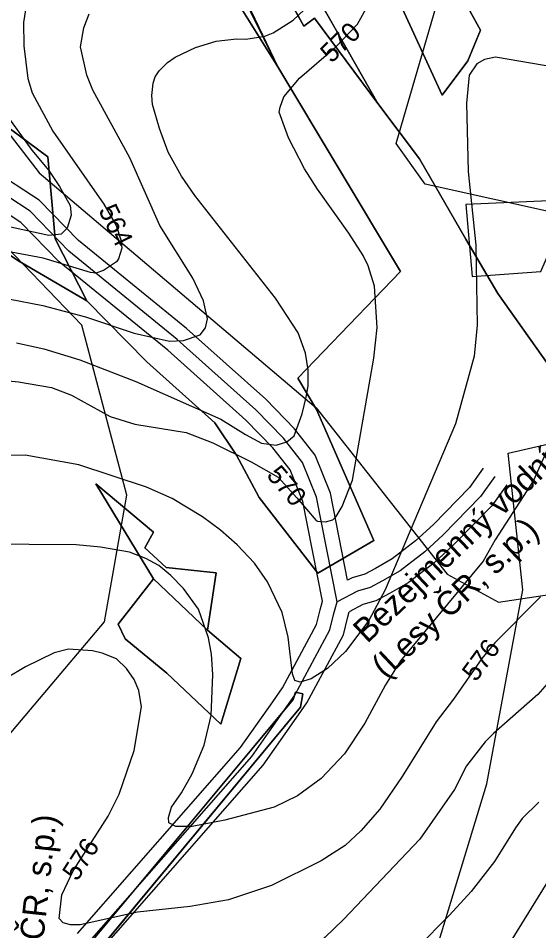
# Model space of a CAD drawing. Extents: x -709418 to -703832, y -1161719 to -1157826.
# Drawn here: x -707249.8 to -707032.1, y -1159514.6 to -1159133.3 of the extents above; entities that cross this region are included whole.
import ezdxf

# ---------------------------------------------------------------- set-up
doc = ezdxf.new("R2010")
doc.units = 0
for name, color, linetype in [('102_obvod PÚ', 7, 'Continuous'), ('106_zastavitelné plochy', 7, 'Continuous'), ('120_vrstevnice hlavní', 7, 'Continuous'), ('121_vrstevnice hlavní_popis', 7, 'Continuous'), ('122_vrstevnice základní', 7, 'Continuous'), ('206_TTP_KN', 7, 'Continuous'), ('207_lesní pozemek_KN', 7, 'Continuous'), ('208_vodní plocha_KN', 7, 'Continuous'), ('210_ostatní plocha_KN', 7, 'Continuous'), ('501_vodní tok', 7, 'Continuous'), ('502_vodní tok_popis', 7, 'Continuous'), ('514 odvodnění - LPIS', 7, 'Continuous'), ('735_OP sítí TI', 7, 'Continuous')]:
    doc.layers.add(name, color=color, linetype=linetype)

msp = doc.modelspace()

# ---------------------------------------------------------------- linework, layer by layer
at = {"layer": '102_obvod PÚ'}
for points in [[(-707090.72, -1159125.66), (-707080.09, -1159102.97), (-707083.45, -1159098.68), (-707081.52, -1159086.91), (-707067.53, -1159081.2), (-707060.25, -1159112.67), (-707060.75, -1159130.51), (-707056.4, -1159138.22), (-707061.68, -1159151.06), (-707072.46, -1159165.41), (-707090.72, -1159125.66)], [(-707090.72, -1159125.66), (-707072.46, -1159165.41), (-707061.68, -1159151.06), (-707056.4, -1159138.22), (-707060.75, -1159130.51), (-707060.25, -1159112.67), (-707067.53, -1159081.2), (-707081.52, -1159086.91), (-707083.45, -1159098.68), (-707080.09, -1159102.97), (-707090.72, -1159125.66)], [(-707163.88, -1159107.46), (-707141.26, -1159153.59), (-707089.94, -1159239.07), (-707132.85, -1159283.71), (-707125, -1159296.84), (-707101.06, -1159351.57), (-707124.48, -1159365.16), (-707148.94, -1159333.63), (-707158.47, -1159315.9), (-707167.56, -1159302.38), (-707196, -1159276.9), (-707221.11, -1159251.31), (-707234.26, -1159225.46), (-707237.4, -1159191.19), (-707264.49, -1159171.23), (-707284.79, -1159147.72)], [(-707284.79, -1159147.72), (-707264.49, -1159171.23), (-707237.4, -1159191.19), (-707234.26, -1159225.46), (-707221.11, -1159251.31), (-707196, -1159276.9), (-707167.56, -1159302.38), (-707158.47, -1159315.9), (-707148.94, -1159333.63), (-707124.48, -1159365.16), (-707101.06, -1159351.57), (-707125, -1159296.84), (-707132.85, -1159283.71), (-707089.94, -1159239.07), (-707141.26, -1159153.59), (-707163.88, -1159107.46)], [(-707207.97, -1159386.5), (-707193.13, -1159367.53), (-707170.58, -1159389.04), (-707156.7, -1159400.84), (-707165.01, -1159428.35), (-707187.56, -1159406.94), (-707205.04, -1159392.67), (-707207.97, -1159386.5)], [(-707207.97, -1159386.5), (-707205.04, -1159392.67), (-707187.56, -1159406.94), (-707165.01, -1159428.35), (-707156.7, -1159400.84), (-707170.58, -1159389.04), (-707193.13, -1159367.53), (-707207.97, -1159386.5)]]:
    msp.add_lwpolyline(points, dxfattribs=at)
at = {"layer": '106_zastavitelné plochy'}
for points in [[(-707062.59, -1159211.18), (-707059.86, -1159241.16), (-707031.23, -1159239.12), (-707018.28, -1159209.13), (-707062.59, -1159211.18)], [(-707081, -1159542.58), (-707053.73, -1159453.31), (-707038.73, -1159372.22), (-707044.86, -1159314.98), (-707006, -1159306.12), (-706981.46, -1159408.34), (-706987.6, -1159458.77), (-707002.6, -1159535.09), (-706999.87, -1159572.57), (-707008.73, -1159578.02), (-707010.09, -1159567.12), (-707032.59, -1159588.24), (-707046.91, -1159588.92), (-707081, -1159542.58)]]:
    msp.add_lwpolyline(points, dxfattribs=at)
at = {"layer": '120_vrstevnice hlavní'}
for points in [[(-707125.17, -1159343.19), (-707124.61, -1159343.46), (-707121.27, -1159343.74), (-707118.2, -1159342.91), (-707116.81, -1159341.51), (-707114.3, -1159337.33), (-707110, -1159326.39), (-707101, -1159275.31), (-707099.71, -1159262.46), (-707100.71, -1159245.31), (-707103.43, -1159236.74), (-707105.57, -1159232.46), (-707111.43, -1159223.03), (-707124.57, -1159204.74), (-707130, -1159196.17), (-707136.71, -1159183.31), (-707140.57, -1159172.59), (-707140.28, -1159170.45), (-707138.71, -1159166.17), (-707132.14, -1159158.31), (-707117, -1159145.17), (-707107.85, -1159135.74), (-707102.85, -1159126.74)], [(-707256.43, -1159284.6), (-707249.58, -1159285.17), (-707235.86, -1159287.6), (-707227.43, -1159290.74), (-707211.29, -1159299.74), (-707201, -1159302.89), (-707179.57, -1159306.46), (-707168.43, -1159310.74), (-707152.28, -1159318.6), (-707141, -1159325.03), (-707133.25, -1159333.71), (-707125.17, -1159343.19)], [(-707031.99, -1159460.89), (-707038.99, -1159467.75), (-707041.85, -1159471.61), (-707050.56, -1159485.74), (-707060.33, -1159498.29), (-707069.45, -1159508.09), (-707096.49, -1159535.5)]]:
    msp.add_lwpolyline(points, dxfattribs=at)
at = {"layer": '122_vrstevnice základní'}
for points in [[(-707200.52, -1159285.11), (-707165.03, -1159300.87), (-707154.72, -1159307.28), (-707148.03, -1159310.91), (-707141.89, -1159311.74), (-707137.44, -1159310.35), (-707134.37, -1159307.84), (-707131.02, -1159298.64), (-707129.35, -1159291.67), (-707128.52, -1159286.93), (-707128.57, -1159280.17), (-707129.57, -1159273.31), (-707132.71, -1159264.74), (-707142.14, -1159250.31), (-707175.86, -1159207.31), (-707181.43, -1159199.31), (-707187, -1159189.31), (-707190.71, -1159179.31), (-707193.57, -1159169.31), (-707193.86, -1159165.59), (-707193.29, -1159160.45), (-707192.43, -1159157.74), (-707190.86, -1159155.31), (-707187.29, -1159151.74), (-707184.14, -1159149.59), (-707175.57, -1159145.45), (-707167, -1159142.88), (-707158.43, -1159141.88), (-707154.56, -1159142.04), (-707146.57, -1159140.74), (-707143.14, -1159139.31), (-707134.71, -1159134.02), (-707118.28, -1159118.45)], [(-707271.43, -1159130.45), (-707271.29, -1159139.88), (-707269, -1159147.88), (-707264.29, -1159157.88), (-707254.57, -1159173.88), (-707244, -1159188.45), (-707237, -1159196.88), (-707232.43, -1159203.6), (-707228, -1159211.6), (-707227.57, -1159215.6), (-707229.29, -1159221.03), (-707231.86, -1159223.45), (-707237, -1159224.03), (-707265.3, -1159217.9), (-707277.07, -1159216.13)], [(-707246.43, -1159127.88), (-707247.57, -1159135.02), (-707247.43, -1159144.74), (-707245.72, -1159158.45), (-707243.86, -1159164.45), (-707235.29, -1159180.45), (-707214, -1159211.03), (-707208.86, -1159219.88), (-707206.86, -1159225.88), (-707206.43, -1159229.31), (-707207.86, -1159233.88), (-707208.72, -1159235.03), (-707214.14, -1159238.74), (-707217.29, -1159239.88), (-707219.57, -1159239.6), (-707239.37, -1159233.52), (-707254.88, -1159230.62)], [(-706978.28, -1159127.59), (-706994.13, -1159142.74), (-707000.13, -1159147.31), (-707006.71, -1159150.88), (-707011.28, -1159152.59), (-707018.14, -1159153.88), (-707024.99, -1159153.88), (-707050.14, -1159149.59), (-707054.71, -1159150.45), (-707057.99, -1159152.31), (-707061.14, -1159157.02), (-707062.28, -1159168.74), (-707061.57, -1159197.31), (-707058.42, -1159228.17), (-707057.85, -1159261.6), (-707059.14, -1159274.46), (-707066.85, -1159302.74), (-707096.28, -1159372.18)], [(-707253.79, -1159250.6), (-707239.5, -1159253.32), (-707221.59, -1159258.1), (-707201.26, -1159264.94), (-707186.49, -1159268.24), (-707180.64, -1159267.96), (-707173.71, -1159265.6), (-707171.44, -1159262.67), (-707170.57, -1159258.88), (-707172.29, -1159251.31), (-707176.71, -1159241.88), (-707190.57, -1159219.88), (-707203.14, -1159191.6), (-707218.57, -1159163.31), (-707221, -1159157.02), (-707223.72, -1159145.17), (-707222.29, -1159137.31), (-707220.15, -1159131.45)], [(-707250.44, -1159268.88), (-707239.08, -1159271.44), (-707223.94, -1159276.05), (-707200.52, -1159285.11)], [(-707027.99, -1159312.46), (-707034.28, -1159326.46), (-707050.28, -1159351.32), (-707055.28, -1159360.18), (-707089.85, -1159401.89), (-707096.14, -1159411.89), (-707104.85, -1159427.89), (-707113.28, -1159440.75), (-707123, -1159451.04), (-707133, -1159458.32), (-707142.71, -1159463.04), (-707163.29, -1159468.47), (-707177, -1159471.04), (-707183.86, -1159471.04), (-707186.71, -1159469.61), (-707186.86, -1159467.32), (-707185.71, -1159463.04), (-707181.43, -1159457.04), (-707177, -1159449.04), (-707172, -1159437.04), (-707169.14, -1159424.75), (-707168.43, -1159407.61), (-707169, -1159399.03), (-707170.14, -1159392.18), (-707174.43, -1159380.18), (-707180.71, -1159371.6), (-707186, -1159366.18), (-707191, -1159362.03), (-707196.43, -1159359.03), (-707203.29, -1159356.46), (-707215.29, -1159354.32), (-707225.57, -1159353.32), (-707265, -1159353.03)], [(-707096.28, -1159372.18), (-707103.14, -1159385.03), (-707112.85, -1159397.89), (-707120.43, -1159405.03), (-707127.28, -1159409.32), (-707131.85, -1159410.75), (-707134.14, -1159410.03), (-707135, -1159407.32), (-707136.85, -1159391.89), (-707139.43, -1159381.6), (-707145.57, -1159368.75), (-707151, -1159361.03), (-707158.14, -1159353.32), (-707165.14, -1159347.17), (-707172.71, -1159341.6), (-707185.43, -1159334.03), (-707196.14, -1159329.32), (-707224.43, -1159319.89), (-707246.89, -1159315.83), (-707261.84, -1159316.2)], [(-707031.28, -1159375.03), (-707050.42, -1159394.32), (-707055.85, -1159400.89), (-707067.71, -1159417.89), (-707074.99, -1159427.32), (-707089.14, -1159450.18), (-707098.57, -1159463.89), (-707106.42, -1159472.9), (-707113, -1159479.04), (-707123, -1159485.47), (-707143.85, -1159495.75), (-707161.86, -1159501.75), (-707177.86, -1159504.47), (-707199.86, -1159506.9), (-707223.86, -1159512.18), (-707227.86, -1159512.18), (-707231, -1159511.32), (-707232.57, -1159509.47), (-707231.57, -1159499.61), (-707226.72, -1159489.61), (-707212.14, -1159466.75), (-707207.57, -1159457.61), (-707201.29, -1159439.32), (-707198.14, -1159421.04), (-707199.29, -1159414.18), (-707201.29, -1159409.61), (-707204.43, -1159405.03), (-707208.72, -1159401.03), (-707214.72, -1159398.6), (-707218.72, -1159397.6), (-707228.72, -1159397.03), (-707234.72, -1159398.46), (-707246.72, -1159404.32), (-707254.72, -1159409.03)], [(-707016.85, -1159398.03), (-707032.42, -1159415.89), (-707050.99, -1159432.18), (-707054.42, -1159435.75), (-707062.28, -1159445.75), (-707067.28, -1159455.61), (-707081.85, -1159476.32), (-707113.73, -1159510.01), (-707121.54, -1159517.53), (-707136.55, -1159530.6)], [(-707024.71, -1159488.04), (-707044.05, -1159519.36), (-707058.68, -1159540.12)]]:
    msp.add_lwpolyline(points, dxfattribs=at)
at = {"layer": '206_TTP_KN'}
for p, q in [((-707217.27, -1159327.83), (-707193.15, -1159348.1)), ((-707193.13, -1159367.53), (-707217.27, -1159327.83)), ((-707193.15, -1159348.1), (-707196.77, -1159354.61)), ((-707196.77, -1159354.61), (-707187.89, -1159362.89)), ((-707187.89, -1159362.89), (-707166.98, -1159365.07)), ((-707170.58, -1159389.04), (-707193.13, -1159367.53)), ((-707166.98, -1159365.07), (-707170.58, -1159389.04))]:
    msp.add_line(p, q, dxfattribs=at)
for points in [[(-707163.23, -1159076.48), (-707130.37, -1159136.64), (-707125.81, -1159133.29), (-707099.33, -1159168.86), (-707082, -1159191.97), (-707062.59, -1159225.65), (-707049.17, -1159248.27), (-707028.19, -1159278.03)], [(-707090.72, -1159125.66), (-707072.46, -1159165.41), (-707061.68, -1159151.06), (-707056.4, -1159138.22), (-707060.75, -1159130.51), (-707060.25, -1159112.67), (-707067.53, -1159081.2), (-707081.52, -1159086.91), (-707083.45, -1159098.68), (-707080.09, -1159102.97), (-707090.72, -1159125.66)], [(-707016.26, -1159123.62), (-706985.49, -1159170.3), (-707014.99, -1159245.85), (-707017.92, -1159260.69), (-707009.21, -1159302.72), (-707014.36, -1159296.7), (-707019.13, -1159291.16), (-707028.19, -1159278.03), (-707049.17, -1159248.27), (-707062.59, -1159225.65), (-707082, -1159191.97), (-707099.33, -1159168.86), (-707112.14, -1159146.31), (-707131.59, -1159112.27)], [(-707470.01, -1159128.4), (-707440.09, -1159137.73), (-707419.92, -1159149.19), (-707419.85, -1159160.97), (-707396.66, -1159177.74), (-707367.26, -1159195.86), (-707316.09, -1159206.21), (-707285.26, -1159210.99), (-707249.87, -1159234.47), (-707221.11, -1159251.31), (-707196, -1159276.9), (-707167.56, -1159302.38), (-707158.47, -1159315.9), (-707148.94, -1159333.63), (-707124.48, -1159365.16), (-707101.06, -1159351.57), (-707125, -1159296.84), (-707132.85, -1159283.71), (-707089.94, -1159239.07), (-707141.26, -1159153.59), (-707153.99, -1159126.87)], [(-707217.27, -1159327.83), (-707193.13, -1159367.53), (-707207.97, -1159386.5), (-707205.04, -1159392.67), (-707187.56, -1159406.94), (-707165.01, -1159428.35), (-707156.7, -1159400.84), (-707170.58, -1159389.04), (-707166.98, -1159365.07), (-707187.89, -1159362.89), (-707196.77, -1159354.61), (-707193.15, -1159348.1), (-707217.27, -1159327.83)], [(-707221.95, -1159529.79), (-707131.68, -1159421.18), (-707130.76, -1159415.61), (-707133.83, -1159414.9), (-707134.75, -1159417.97), (-707223.19, -1159524.06)]]:
    msp.add_lwpolyline(points, dxfattribs=at)
at = {"layer": '207_lesní pozemek_KN'}
for p, q in [((-707130.37, -1159136.64), (-707163.23, -1159076.48)), ((-707131.59, -1159112.27), (-707112.14, -1159146.31)), ((-707158.63, -1159125.51), (-707141.26, -1159153.59)), ((-707141.26, -1159153.59), (-707158.63, -1159125.51)), ((-707153.99, -1159126.87), (-707141.26, -1159153.59)), ((-707072.46, -1159165.41), (-707090.72, -1159125.66)), ((-707060.75, -1159130.51), (-707056.4, -1159138.22)), ((-707125.81, -1159133.29), (-707130.37, -1159136.64)), ((-707099.33, -1159168.86), (-707125.81, -1159133.29)), ((-707056.4, -1159138.22), (-707061.68, -1159151.06)), ((-707112.14, -1159146.31), (-707099.33, -1159168.86)), ((-707141.26, -1159153.59), (-707089.94, -1159239.07)), ((-707061.68, -1159151.06), (-707072.46, -1159165.41)), ((-707237.4, -1159191.19), (-707264.49, -1159171.23)), ((-707234.26, -1159225.46), (-707237.4, -1159191.19)), ((-707221.11, -1159251.31), (-707234.26, -1159225.46)), ((-707089.94, -1159239.07), (-707132.85, -1159283.71)), ((-707196, -1159276.9), (-707221.11, -1159251.31)), ((-707167.56, -1159302.38), (-707196, -1159276.9)), ((-707132.85, -1159283.71), (-707125, -1159296.84)), ((-707125, -1159296.84), (-707101.06, -1159351.57)), ((-707158.47, -1159315.9), (-707167.56, -1159302.38)), ((-707148.94, -1159333.63), (-707158.47, -1159315.9)), ((-707124.48, -1159365.16), (-707148.94, -1159333.63)), ((-707101.06, -1159351.57), (-707124.48, -1159365.16)), ((-707207.97, -1159386.5), (-707193.13, -1159367.53)), ((-707193.13, -1159367.53), (-707170.58, -1159389.04)), ((-707205.04, -1159392.67), (-707207.97, -1159386.5)), ((-707170.58, -1159389.04), (-707156.7, -1159400.84)), ((-707187.56, -1159406.94), (-707205.04, -1159392.67)), ((-707156.7, -1159400.84), (-707165.01, -1159428.35)), ((-707165.01, -1159428.35), (-707187.56, -1159406.94))]:
    msp.add_line(p, q, dxfattribs=at)
at = {"layer": '208_vodní plocha_KN'}
for p, q in [((-707134.75, -1159417.97), (-707133.83, -1159414.9)), ((-707133.83, -1159414.9), (-707130.76, -1159415.61)), ((-707130.76, -1159415.61), (-707131.68, -1159421.18)), ((-707223.19, -1159524.06), (-707134.75, -1159417.97)), ((-707131.68, -1159421.18), (-707221.95, -1159529.79))]:
    msp.add_line(p, q, dxfattribs=at)
at = {"layer": '210_ostatní plocha_KN'}
msp.add_lwpolyline([(-707304.89, -1159117.79), (-707278.34, -1159139.92), (-707284.79, -1159147.72), (-707264.49, -1159171.23), (-707237.4, -1159191.19), (-707234.26, -1159225.46), (-707221.11, -1159251.31), (-707249.87, -1159234.47), (-707285.26, -1159210.99), (-707316.09, -1159206.21), (-707367.26, -1159195.86), (-707396.66, -1159177.74), (-707419.85, -1159160.97), (-707419.92, -1159149.19)], dxfattribs=at)
at = {"layer": '501_vodní tok'}
for points in [[(-707220.89, -1159520.28), (-707152.09, -1159441.77), (-707138.44, -1159422.37), (-707134.12, -1159416.24), (-707119.42, -1159388.85), (-707117.71, -1159382), (-707116.4, -1159377.18), (-707124.99, -1159333.5), (-707130.84, -1159318.95), (-707138.81, -1159308.8), (-707150.39, -1159296.87), (-707183.24, -1159267.49), (-707228.62, -1159230.63), (-707244.82, -1159213.95), (-707263.65, -1159201.68), (-707276.2, -1159195.83), (-707339.26, -1159172.87), (-707386.33, -1159158.32), (-707402.06, -1159150.83), (-707413.32, -1159145.37), (-707431.27, -1159133.64), (-707440.11, -1159121.8)], [(-707050.38, -1159324.79), (-707056.37, -1159333.21), (-707071.98, -1159349.22), (-707079.76, -1159356.35), (-707090.01, -1159364.18), (-707097.42, -1159368.46), (-707102.54, -1159371.13), (-707107.86, -1159372.73), (-707116.4, -1159377.18)]]:
    msp.add_lwpolyline(points, dxfattribs=at)
at = {"layer": '514 odvodnění - LPIS'}
for points in [[(-707027.07, -1159697.45), (-707188.93, -1159777.54), (-707224.81, -1159766.62), (-707366.22, -1159601.86), (-707359.1, -1159546.42), (-707312.11, -1159509), (-707278.01, -1159461.46), (-707213.69, -1159385.57), (-707204.36, -1159332.63), (-707223.13, -1159261.51), (-707265.16, -1159218.13), (-707292.46, -1159182.37), (-707478.88, -1159157.27), (-707497.47, -1159147.65), (-707457.12, -1159066.36)], [(-706467.73, -1159088.95), (-706475.67, -1159141.26), (-706583.02, -1159153.02), (-706622.19, -1159157.59), (-706795.72, -1159207.77), (-706994.66, -1159221.4), (-707079.58, -1159202.66), (-707091.66, -1159185.61), (-707067.05, -1159100.92)], [(-707303.87, -1159096.76), (-707286.56, -1159139.02), (-707240.99, -1159197.93), (-707125.22, -1159296.13), (-707070.39, -1159365.62), (-707048.97, -1159377.37), (-707017.4, -1159372.65)]]:
    msp.add_lwpolyline(points, dxfattribs=at)
at = {"layer": '735_OP sítí TI'}
for points in [[(-707224.95, -1159515.82), (-707156.82, -1159438.06), (-707143.34, -1159418.92), (-707139.23, -1159413.08), (-707125.06, -1159386.67), (-707123.52, -1159380.49), (-707122.56, -1159376.96), (-707130.77, -1159335.21), (-707136.08, -1159321.99), (-707143.33, -1159312.76), (-707154.55, -1159301.2), (-707187.13, -1159272.06), (-707232.68, -1159235.06), (-707248.66, -1159218.61), (-707266.57, -1159206.94), (-707278.5, -1159201.38), (-707341.17, -1159178.55), (-707388.52, -1159163.92), (-707404.66, -1159156.24), (-707416.29, -1159150.6), (-707435.44, -1159138.08), (-707445.29, -1159124.89)], [(-707112.06, -1159368.15), (-707119.21, -1159331.78), (-707125.59, -1159315.92), (-707134.29, -1159304.85), (-707146.23, -1159292.54), (-707179.35, -1159262.92), (-707224.56, -1159226.19), (-707240.98, -1159209.29), (-707260.73, -1159196.42), (-707273.91, -1159190.29), (-707337.34, -1159167.18), (-707384.15, -1159152.71), (-707399.46, -1159145.42), (-707410.36, -1159140.14), (-707427.1, -1159129.19)], [(-707055.27, -1159321.31), (-707060.99, -1159329.35), (-707076.15, -1159344.91), (-707083.62, -1159351.74), (-707093.35, -1159359.18), (-707100.31, -1159363.19), (-707104.82, -1159365.55), (-707110.13, -1159367.15), (-707112.06, -1159368.15)], [(-707045.49, -1159328.27), (-707051.75, -1159337.07), (-707067.8, -1159353.54), (-707075.91, -1159360.95), (-707086.68, -1159369.19), (-707094.53, -1159373.72), (-707100.27, -1159376.71), (-707105.59, -1159378.31), (-707111.3, -1159381.29)], [(-707216.83, -1159524.75), (-707147.37, -1159445.49), (-707133.53, -1159425.82), (-707129, -1159419.39), (-707113.78, -1159391.03), (-707111.91, -1159383.51), (-707111.3, -1159381.29)]]:
    msp.add_lwpolyline(points, dxfattribs=at)

# ---------------------------------------------------------------- texts
at = {"layer": '121_vrstevnice hlavní_popis'}
for s, rotation, p in [('570', 43.9709, (-707118.74, -1159152.35)), ('564', 295.7802, (-707216.36, -1159213.42)), ('570', 310.5742, (-707146.26, -1159324.46)), ('576', 53.7094, (-707058.36, -1159410.97)), ('576', 57.2764, (-707225.13, -1159494.32))]:
    msp.add_text(s, height=8, rotation=rotation, dxfattribs=at).set_placement(p)
at = {"layer": '502_vodní tok_popis'}
for s, rotation, p in [('Bezejmenný vodní tok 01', 43.364, (-707103.84, -1159394.85)), ('(Lesy ČR, s.p.)', 43.364, (-707096.14, -1159409.63)), ('Kunějovský potok (Lesy ČR, s.p.)', 83.7769, (-707254.98, -1159663.1))]:
    msp.add_text(s, height=10, rotation=rotation, dxfattribs=at).set_placement(p)

doc.saveas('drawing.dxf')
